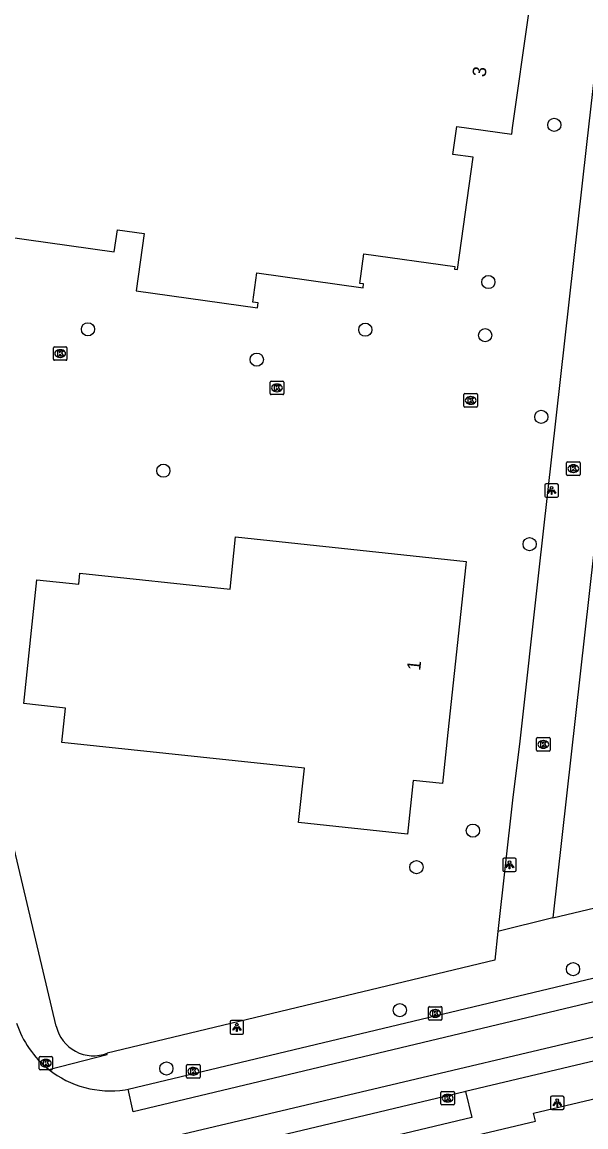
# Model space of a CAD drawing. Extents: x 162082 to 163393, y 388091 to 388632.
# Drawn here: x 162963.6 to 163005.4, y 388261.2 to 388343.1 of the extents above; entities that cross this region are included whole.
import ezdxf

# ---------------------------------------------------------------- set-up
doc = ezdxf.new("R2010")
doc.units = 0
for name, color, linetype in [('IMGEO_Boom', 7, 'Continuous'), ('IMGEO_Kolk', 7, 'Continuous'), ('IMGEO_Lichtpunt', 7, 'Continuous'), ('IMGEO_Pand', 7, 'Continuous'), ('IMGEO_Pand_nummerreeks', 7, 'Continuous'), ('IMGEO_Rijbaan_lokaal_gesloten', 7, 'Continuous'), ('IMGEO_Voetpad_open', 7, 'Continuous')]:
    doc.layers.add(name, color=color, linetype=linetype)

msp = doc.modelspace()

# ---------------------------------------------------------------- linework, layer by layer
at = {"layer": 'IMGEO_Boom'}
for centre in [(163003.085, 388335.514), (162998.2, 388323.859), (162968.519, 388320.354), (162989.078, 388320.325), (162997.959, 388319.915), (162981.031, 388318.106), (163002.121, 388313.858), (162974.111, 388309.867), (163001.259, 388304.418), (162997.055, 388283.177), (162992.866, 388280.467), (163004.475, 388272.897), (162991.638, 388269.857), (162974.33, 388265.53)]:
    msp.add_circle(centre, 0.489, dxfattribs=at)
at = {"layer": 'IMGEO_Kolk'}
for p, q in [((162965.963, 388318.13), (162965.963, 388318.982)), ((162966.038, 388319.056), (162966.89, 388319.056)), ((162966.451, 388318.836), (162966.476, 388318.836)), ((162966.964, 388318.982), (162966.964, 388318.13)), ((162966.89, 388318.056), (162966.038, 388318.056)), ((162966.474, 388318.276), (162966.449, 388318.276)), ((162982.027, 388315.584), (162982.027, 388316.436)), ((162982.102, 388316.51), (162982.954, 388316.51)), ((162982.515, 388316.29), (162982.54, 388316.29)), ((162983.028, 388316.436), (162983.028, 388315.584)), ((162982.954, 388315.51), (162982.102, 388315.51)), ((162982.538, 388315.73), (162982.513, 388315.73)), ((162996.391, 388314.657), (162996.391, 388315.509)), ((162996.466, 388315.583), (162997.318, 388315.583)), ((162997.392, 388315.509), (162997.392, 388314.657)), ((162997.318, 388314.583), (162996.466, 388314.583)), ((162996.902, 388314.803), (162996.877, 388314.803)), ((162996.879, 388315.363), (162996.904, 388315.363)), ((163004.075, 388310.523), (163004.927, 388310.523)), ((163004, 388309.597), (163004, 388310.449)), ((163004.511, 388309.743), (163004.486, 388309.743)), ((163004.488, 388310.303), (163004.513, 388310.303)), ((163005.001, 388310.449), (163005.001, 388309.597)), ((163004.927, 388309.523), (163004.075, 388309.523)), ((163001.772, 388289.146), (163001.772, 388289.998)), ((163001.847, 388290.072), (163002.699, 388290.072)), ((163002.773, 388289.998), (163002.773, 388289.146)), ((163002.283, 388289.292), (163002.258, 388289.292)), ((163002.26, 388289.852), (163002.285, 388289.852)), ((163002.699, 388289.072), (163001.847, 388289.072)), ((162993.76, 388269.194), (162993.76, 388270.046)), ((162993.835, 388270.12), (162994.687, 388270.12)), ((162994.248, 388269.9), (162994.273, 388269.9)), ((162994.761, 388270.046), (162994.761, 388269.194)), ((162994.687, 388269.12), (162993.835, 388269.12)), ((162994.271, 388269.34), (162994.246, 388269.34)), ((162964.898, 388265.5), (162964.898, 388266.352)), ((162964.973, 388266.426), (162965.825, 388266.426)), ((162965.899, 388266.352), (162965.899, 388265.5)), ((162965.825, 388265.426), (162964.973, 388265.426)), ((162965.409, 388265.646), (162965.384, 388265.646)), ((162965.386, 388266.206), (162965.411, 388266.206)), ((162975.829, 388264.9), (162975.829, 388265.752)), ((162975.904, 388265.826), (162976.756, 388265.826)), ((162976.317, 388265.606), (162976.342, 388265.606)), ((162976.83, 388265.752), (162976.83, 388264.9)), ((162976.756, 388264.826), (162975.904, 388264.826)), ((162976.34, 388265.046), (162976.315, 388265.046)), ((162994.682, 388262.912), (162994.682, 388263.764)), ((162994.757, 388263.838), (162995.609, 388263.838)), ((162995.683, 388263.764), (162995.683, 388262.912)), ((162995.193, 388263.058), (162995.168, 388263.058)), ((162995.17, 388263.618), (162995.195, 388263.618)), ((162995.609, 388262.838), (162994.757, 388262.838))]:
    msp.add_line(p, q, dxfattribs=at)
for points in [[(162965.963, 388318.13), (162965.963, 388318.982)], [(162966.038, 388319.056), (162966.89, 388319.056)], [(162966.284, 388318.756), (162966.407, 388318.756), (162966.407, 388318.605), (162966.537, 388318.756), (162966.701, 388318.756), (162966.555, 388318.605), (162966.708, 388318.356), (162966.556, 388318.356), (162966.471, 388318.52), (162966.407, 388318.453), (162966.407, 388318.356), (162966.284, 388318.356), (162966.284, 388318.756)], [(162966.964, 388318.982), (162966.964, 388318.13)], [(162966.89, 388318.056), (162966.038, 388318.056)], [(162982.027, 388315.584), (162982.027, 388316.436)], [(162982.102, 388316.51), (162982.954, 388316.51)], [(162982.348, 388316.21), (162982.471, 388316.21), (162982.471, 388316.059), (162982.601, 388316.21), (162982.765, 388316.21), (162982.619, 388316.059), (162982.772, 388315.81), (162982.62, 388315.81), (162982.535, 388315.974), (162982.471, 388315.907), (162982.471, 388315.81), (162982.348, 388315.81), (162982.348, 388316.21)], [(162983.028, 388316.436), (162983.028, 388315.584)], [(162982.954, 388315.51), (162982.102, 388315.51)], [(162996.391, 388314.657), (162996.391, 388315.509)], [(162996.466, 388315.583), (162997.318, 388315.583)], [(162997.392, 388315.509), (162997.392, 388314.657)], [(162997.318, 388314.583), (162996.466, 388314.583)], [(162996.712, 388315.283), (162996.835, 388315.283), (162996.835, 388315.132), (162996.965, 388315.283), (162997.129, 388315.283), (162996.983, 388315.132), (162997.136, 388314.883), (162996.984, 388314.883), (162996.899, 388315.047), (162996.835, 388314.98), (162996.835, 388314.883), (162996.712, 388314.883), (162996.712, 388315.283)], [(163004.075, 388310.523), (163004.927, 388310.523)], [(163004, 388309.597), (163004, 388310.449)], [(163004.321, 388310.223), (163004.444, 388310.223), (163004.444, 388310.072), (163004.574, 388310.223), (163004.738, 388310.223), (163004.592, 388310.072), (163004.745, 388309.823), (163004.593, 388309.823), (163004.508, 388309.987), (163004.444, 388309.92), (163004.444, 388309.823), (163004.321, 388309.823), (163004.321, 388310.223)], [(163005.001, 388310.449), (163005.001, 388309.597)], [(163004.927, 388309.523), (163004.075, 388309.523)], [(163001.772, 388289.146), (163001.772, 388289.998)], [(163001.847, 388290.072), (163002.699, 388290.072)], [(163002.773, 388289.998), (163002.773, 388289.146)], [(163002.093, 388289.772), (163002.216, 388289.772), (163002.216, 388289.621), (163002.346, 388289.772), (163002.51, 388289.772), (163002.364, 388289.621), (163002.517, 388289.372), (163002.365, 388289.372), (163002.28, 388289.536), (163002.216, 388289.469), (163002.216, 388289.372), (163002.093, 388289.372), (163002.093, 388289.772)], [(163002.699, 388289.072), (163001.847, 388289.072)], [(162993.76, 388269.194), (162993.76, 388270.046)], [(162993.835, 388270.12), (162994.687, 388270.12)], [(162994.081, 388269.82), (162994.204, 388269.82), (162994.204, 388269.669), (162994.334, 388269.82), (162994.498, 388269.82), (162994.352, 388269.669), (162994.505, 388269.42), (162994.353, 388269.42), (162994.268, 388269.584), (162994.204, 388269.517), (162994.204, 388269.42), (162994.081, 388269.42), (162994.081, 388269.82)], [(162994.761, 388270.046), (162994.761, 388269.194)], [(162994.687, 388269.12), (162993.835, 388269.12)], [(162964.898, 388265.5), (162964.898, 388266.352)], [(162964.973, 388266.426), (162965.825, 388266.426)], [(162965.899, 388266.352), (162965.899, 388265.5)], [(162965.825, 388265.426), (162964.973, 388265.426)], [(162965.219, 388266.126), (162965.342, 388266.126), (162965.342, 388265.975), (162965.472, 388266.126), (162965.636, 388266.126), (162965.49, 388265.975), (162965.643, 388265.726), (162965.491, 388265.726), (162965.406, 388265.89), (162965.342, 388265.823), (162965.342, 388265.726), (162965.219, 388265.726), (162965.219, 388266.126)], [(162975.829, 388264.9), (162975.829, 388265.752)], [(162975.904, 388265.826), (162976.756, 388265.826)], [(162976.15, 388265.526), (162976.273, 388265.526), (162976.273, 388265.375), (162976.403, 388265.526), (162976.567, 388265.526), (162976.421, 388265.375), (162976.574, 388265.126), (162976.422, 388265.126), (162976.337, 388265.29), (162976.273, 388265.223), (162976.273, 388265.126), (162976.15, 388265.126), (162976.15, 388265.526)], [(162976.83, 388265.752), (162976.83, 388264.9)], [(162976.756, 388264.826), (162975.904, 388264.826)], [(162994.682, 388262.912), (162994.682, 388263.764)], [(162994.757, 388263.838), (162995.609, 388263.838)], [(162995.683, 388263.764), (162995.683, 388262.912)], [(162995.003, 388263.538), (162995.126, 388263.538), (162995.126, 388263.387), (162995.256, 388263.538), (162995.42, 388263.538), (162995.274, 388263.387), (162995.427, 388263.138), (162995.275, 388263.138), (162995.19, 388263.302), (162995.126, 388263.235), (162995.126, 388263.138), (162995.003, 388263.138), (162995.003, 388263.538)], [(162995.609, 388262.838), (162994.757, 388262.838)]]:
    msp.add_lwpolyline(points, dxfattribs=at)
for centre, start, end in [((162966.04, 388318.98), 91.55205, 178.44795), ((162966.04, 388318.98), 91.55205, 178.44795), ((162966.888, 388318.98), 1.55205, 88.44795), ((162966.888, 388318.98), 1.55205, 88.44795), ((162966.04, 388318.132), 181.55205, 268.44795), ((162966.04, 388318.132), 181.55205, 268.44795), ((162966.888, 388318.132), 271.55205, 358.44795), ((162966.888, 388318.132), 271.55205, 358.44795), ((162982.104, 388316.434), 91.55205, 178.44795), ((162982.104, 388316.434), 91.55205, 178.44795), ((162982.952, 388316.434), 1.55205, 88.44795), ((162982.952, 388316.434), 1.55205, 88.44795), ((162982.104, 388315.586), 181.55205, 268.44795), ((162982.104, 388315.586), 181.55205, 268.44795), ((162982.952, 388315.586), 271.55205, 358.44795), ((162982.952, 388315.586), 271.55205, 358.44795), ((162996.468, 388315.507), 91.55205, 178.44795), ((162996.468, 388315.507), 91.55205, 178.44795), ((162997.316, 388315.507), 1.55205, 88.44795), ((162997.316, 388315.507), 1.55205, 88.44795), ((162996.468, 388314.659), 181.55205, 268.44795), ((162996.468, 388314.659), 181.55205, 268.44795), ((162997.316, 388314.659), 271.55205, 358.44795), ((162997.316, 388314.659), 271.55205, 358.44795), ((163004.077, 388310.447), 91.55205, 178.44795), ((163004.077, 388310.447), 91.55205, 178.44795), ((163004.925, 388310.447), 1.55205, 88.44795), ((163004.925, 388310.447), 1.55205, 88.44795), ((163004.077, 388309.599), 181.55205, 268.44795), ((163004.077, 388309.599), 181.55205, 268.44795), ((163004.925, 388309.599), 271.55205, 358.44795), ((163004.925, 388309.599), 271.55205, 358.44795), ((163001.849, 388289.996), 91.55205, 178.44795), ((163001.849, 388289.996), 91.55205, 178.44795), ((163002.697, 388289.996), 1.55205, 88.44795), ((163002.697, 388289.996), 1.55205, 88.44795), ((163001.849, 388289.148), 181.55205, 268.44795), ((163001.849, 388289.148), 181.55205, 268.44795), ((163002.697, 388289.148), 271.55205, 358.44795), ((163002.697, 388289.148), 271.55205, 358.44795), ((162993.837, 388270.044), 91.55205, 178.44795), ((162993.837, 388270.044), 91.55205, 178.44795), ((162994.685, 388270.044), 1.55205, 88.44795), ((162994.685, 388270.044), 1.55205, 88.44795), ((162993.837, 388269.196), 181.55205, 268.44795), ((162993.837, 388269.196), 181.55205, 268.44795), ((162994.685, 388269.196), 271.55205, 358.44795), ((162994.685, 388269.196), 271.55205, 358.44795), ((162964.975, 388266.35), 91.55205, 178.44795), ((162964.975, 388266.35), 91.55205, 178.44795), ((162965.823, 388266.35), 1.55205, 88.44795), ((162965.823, 388266.35), 1.55205, 88.44795), ((162964.975, 388265.502), 181.55205, 268.44795), ((162964.975, 388265.502), 181.55205, 268.44795), ((162965.823, 388265.502), 271.55205, 358.44795), ((162965.823, 388265.502), 271.55205, 358.44795), ((162975.906, 388265.75), 91.55205, 178.44795), ((162975.906, 388265.75), 91.55205, 178.44795), ((162976.754, 388265.75), 1.55205, 88.44795), ((162976.754, 388265.75), 1.55205, 88.44795), ((162975.906, 388264.902), 181.55205, 268.44795), ((162975.906, 388264.902), 181.55205, 268.44795), ((162976.754, 388264.902), 271.55205, 358.44795), ((162976.754, 388264.902), 271.55205, 358.44795), ((162994.759, 388263.762), 91.55205, 178.44795), ((162994.759, 388263.762), 91.55205, 178.44795), ((162995.607, 388263.762), 1.55205, 88.44795), ((162995.607, 388263.762), 1.55205, 88.44795), ((162994.759, 388262.914), 181.55205, 268.44795), ((162994.759, 388262.914), 181.55205, 268.44795), ((162995.607, 388262.914), 271.55205, 358.44795), ((162995.607, 388262.914), 271.55205, 358.44795)]:
    msp.add_arc(centre, 0.0765, start, end, dxfattribs=at)
for centre, major_axis, ratio, start_param, end_param in [((162966.45, 388318.556), (-0.387, 0.002), 0.722429, 4.712389, 7.853982), ((162966.475, 388318.556), (-0.39, 0.002), 0.717154, 1.570796, 4.712389), ((162982.514, 388316.01), (-0.387, 0.002), 0.722429, 4.712389, 7.853982), ((162982.539, 388316.01), (-0.39, 0.002), 0.717154, 1.570796, 4.712389), ((162996.878, 388315.083), (-0.387, 0.002), 0.722429, 4.712389, 7.853982), ((162996.903, 388315.083), (-0.39, 0.002), 0.717154, 1.570796, 4.712389), ((163004.487, 388310.023), (-0.387, 0.002), 0.722429, 4.712389, 7.853982), ((163004.512, 388310.023), (-0.39, 0.002), 0.717154, 1.570796, 4.712389), ((163002.259, 388289.572), (-0.387, 0.002), 0.722429, 4.712389, 7.853982), ((163002.284, 388289.572), (-0.39, 0.002), 0.717154, 1.570796, 4.712389), ((162994.247, 388269.62), (-0.387, 0.002), 0.722429, 4.712389, 7.853982), ((162994.272, 388269.62), (-0.39, 0.002), 0.717154, 1.570796, 4.712389), ((162965.385, 388265.926), (-0.387, 0.002), 0.722429, 4.712389, 7.853982), ((162965.41, 388265.926), (-0.39, 0.002), 0.717154, 1.570796, 4.712389), ((162976.316, 388265.326), (-0.387, 0.002), 0.722429, 4.712389, 7.853982), ((162976.341, 388265.326), (-0.39, 0.002), 0.717154, 1.570796, 4.712389), ((162995.169, 388263.338), (-0.387, 0.002), 0.722429, 4.712389, 7.853982), ((162995.194, 388263.338), (-0.39, 0.002), 0.717154, 1.570796, 4.712389)]:
    msp.add_ellipse(centre, major_axis=major_axis, ratio=ratio, start_param=start_param, end_param=end_param, dxfattribs=at)
at = {"layer": 'IMGEO_Lichtpunt'}
for p, q in [((163003.294, 388308.894), (163002.486, 388308.894)), ((163003.294, 388308.894), (163002.486, 388308.894)), ((163002.392, 388308.799), (163002.392, 388307.992)), ((163002.392, 388308.799), (163002.392, 388307.992)), ((163003.388, 388307.992), (163003.388, 388308.799)), ((163003.388, 388307.992), (163003.388, 388308.799)), ((163002.486, 388307.898), (163003.294, 388307.898)), ((163002.486, 388307.898), (163003.294, 388307.898)), ((162999.269, 388281.043), (162999.269, 388280.236)), ((162999.269, 388281.043), (162999.269, 388280.236)), ((163000.171, 388281.138), (162999.363, 388281.138)), ((163000.171, 388281.138), (162999.363, 388281.138)), ((163000.265, 388280.236), (163000.265, 388281.043)), ((163000.265, 388280.236), (163000.265, 388281.043)), ((162999.363, 388280.142), (163000.171, 388280.142)), ((162999.363, 388280.142), (163000.171, 388280.142)), ((162979.062, 388268.991), (162979.062, 388268.184)), ((162979.062, 388268.991), (162979.062, 388268.184)), ((162979.964, 388269.086), (162979.156, 388269.086)), ((162979.964, 388269.086), (162979.156, 388269.086)), ((162980.058, 388268.184), (162980.058, 388268.991)), ((162980.058, 388268.184), (162980.058, 388268.991)), ((162979.156, 388268.09), (162979.964, 388268.09)), ((162979.156, 388268.09), (162979.964, 388268.09)), ((163002.812, 388263.392), (163002.812, 388262.585)), ((163002.812, 388263.392), (163002.812, 388262.585)), ((163003.714, 388263.487), (163002.906, 388263.487)), ((163003.714, 388263.487), (163002.906, 388263.487)), ((163003.808, 388262.585), (163003.808, 388263.392)), ((163003.808, 388262.585), (163003.808, 388263.392)), ((163002.906, 388262.491), (163003.714, 388262.491)), ((163002.906, 388262.491), (163003.714, 388262.491))]:
    msp.add_line(p, q, dxfattribs=at)
for points in [[(163002.766, 388308.463), (163002.805, 388308.435), (163002.617, 388308.173), (163002.579, 388308.2), (163002.766, 388308.463)], [(163002.868, 388308.415), (163002.915, 388308.415), (163002.915, 388308.093), (163002.868, 388308.093), (163002.868, 388308.415)], [(163002.978, 388308.435), (163003.016, 388308.462), (163003.203, 388308.2), (163003.164, 388308.172), (163002.978, 388308.435)], [(162999.643, 388280.707), (162999.682, 388280.679), (162999.494, 388280.417), (162999.456, 388280.444), (162999.643, 388280.707)], [(162999.745, 388280.659), (162999.792, 388280.659), (162999.792, 388280.337), (162999.745, 388280.337), (162999.745, 388280.659)], [(162999.855, 388280.679), (162999.893, 388280.706), (163000.08, 388280.444), (163000.041, 388280.416), (162999.855, 388280.679)], [(162979.436, 388268.655), (162979.475, 388268.627), (162979.287, 388268.365), (162979.249, 388268.392), (162979.436, 388268.655)], [(162979.538, 388268.607), (162979.585, 388268.607), (162979.585, 388268.285), (162979.538, 388268.285), (162979.538, 388268.607)], [(162979.648, 388268.627), (162979.686, 388268.654), (162979.873, 388268.392), (162979.834, 388268.364), (162979.648, 388268.627)], [(163003.186, 388263.056), (163003.225, 388263.028), (163003.037, 388262.766), (163002.999, 388262.793), (163003.186, 388263.056)], [(163003.288, 388263.008), (163003.335, 388263.008), (163003.335, 388262.686), (163003.288, 388262.686), (163003.288, 388263.008)], [(163003.398, 388263.028), (163003.436, 388263.055), (163003.623, 388262.793), (163003.584, 388262.765), (163003.398, 388263.028)]]:
    msp.add_lwpolyline(points, dxfattribs=at)
for centre in [(163002.891, 388308.597), (162999.768, 388280.841), (162979.561, 388268.789), (163003.311, 388263.19)]:
    msp.add_circle(centre, 0.0994, dxfattribs=at)
for centre, start, end in [((163002.486, 388308.799), 90, 180), ((163002.486, 388308.799), 90, 180), ((163003.294, 388308.799), 0, 90), ((163003.294, 388308.799), 0, 90), ((163002.486, 388307.992), 180, 270), ((163002.486, 388307.992), 180, 270), ((163003.294, 388307.992), 270, 0), ((163003.294, 388307.992), 270, 360), ((162999.363, 388281.043), 90, 180), ((162999.363, 388281.043), 90, 180), ((163000.171, 388281.043), 0, 90), ((163000.171, 388281.043), 0, 90), ((162999.363, 388280.236), 180, 270), ((162999.363, 388280.236), 180, 270), ((163000.171, 388280.236), 270, 0), ((163000.171, 388280.236), 270, 360), ((162979.156, 388268.991), 90, 180), ((162979.156, 388268.991), 90, 180), ((162979.964, 388268.991), 0, 90), ((162979.964, 388268.991), 0, 90), ((162979.156, 388268.184), 180, 270), ((162979.156, 388268.184), 180, 270), ((162979.964, 388268.184), 270, 0), ((162979.964, 388268.184), 270, 360), ((163002.906, 388263.392), 90, 180), ((163002.906, 388263.392), 90, 180), ((163003.714, 388263.392), 0, 90), ((163003.714, 388263.392), 0, 90), ((163002.906, 388262.585), 180, 270), ((163002.906, 388262.585), 180, 270), ((163003.714, 388262.585), 270, 0), ((163003.714, 388262.585), 270, 360)]:
    msp.add_arc(centre, 0.0946, start, end, dxfattribs=at)
at = {"layer": 'IMGEO_Pand'}
for points in [[(162962.21, 388327.258), (162970.473, 388326.096), (162970.705, 388327.745), (162972.698, 388327.465), (162972.099, 388323.204), (162981.092, 388321.94), (162981.146, 388322.322), (162980.734, 388322.38), (162981.036, 388324.532), (162988.911, 388323.425), (162988.952, 388323.716), (162988.67, 388323.755), (162988.979, 388325.951), (162995.709, 388325.005), (162995.684, 388324.824), (162995.914, 388324.792), (162997.084, 388333.113), (162995.569, 388333.326), (162995.862, 388335.406), (162999.936, 388334.833), (163000, 388335.288), (163001.195, 388343.791)], [(162996.548, 388303.138), (162996.52, 388302.879), (162995.194, 388290.457), (162994.79, 388286.669), (162992.627, 388286.9), (162992.201, 388282.906), (162984.128, 388283.768), (162984.559, 388287.803), (162966.581, 388289.722), (162966.852, 388292.264), (162964.864, 388292.476), (162963.755, 388292.594), (162964.735, 388301.773), (162967.832, 388301.442), (162967.921, 388302.275), (162979.053, 388301.087), (162979.466, 388304.962), (162996.548, 388303.138)]]:
    msp.add_lwpolyline(points, dxfattribs=at)
at = {"layer": 'IMGEO_Rijbaan_lokaal_gesloten'}
for points in [[(163022.672, 388276.234), (163023.09, 388274.56), (162971.872, 388262.319), (162971.492, 388264.011)], [(162971.492, 388264.011), (163008.218, 388272.782)], [(162972.884, 388258.2), (162972.452, 388259.959), (163023.671, 388272.065), (163024.112, 388270.399)], [(163009.956, 388267.016), (162996.51, 388263.828)], [(162971.268, 388263.958), (162971.492, 388264.011)], [(162996.51, 388263.828), (162996.44, 388263.811), (162972.884, 388258.2)]]:
    msp.add_lwpolyline(points, dxfattribs=at)
for centre, radius, start, end in [((162970.158, 388271.174), 7.293, 198.11171, 231.48453), ((162970.171, 388271.182), 7.307, 231.44456, 278.63455)]:
    msp.add_arc(centre, radius, start, end, dxfattribs=at)
at = {"layer": 'IMGEO_Voetpad_open'}
for points in [[(163009.556, 388370.497), (163009.548, 388370.428), (163008.683, 388363.066), (163008.493, 388360.713), (163005.462, 388334.056), (163001.924, 388302.296), (163000.525, 388289.822), (163000, 388285.427), (162998.906, 388275.686)], [(163013.441, 388370.076), (163002.97, 388276.7)], [(162966.17, 388268.679), (162961.187, 388289.582), (162960.82, 388291.119), (162953.166, 388323.228), (162952.976, 388324.023)], [(163002.97, 388276.7), (163142.597, 388309.979)], [(163002.97, 388276.7), (162998.906, 388275.686)], [(162998.906, 388275.686), (162998.667, 388273.56), (162969.954, 388266.671)], [(162986.413, 388255.159), (162985.767, 388257.851), (163001.699, 388261.631), (163001.557, 388262.213), (163019.583, 388266.507), (163023.493, 388267.421)], [(162965.617, 388265.468), (162969.935, 388266.571), (162969.954, 388266.671)], [(162996.51, 388263.828), (162996.971, 388261.896), (162955.043, 388251.888), (162954.592, 388253.843)]]:
    msp.add_lwpolyline(points, dxfattribs=at)
msp.add_arc((162968.929, 388269.308), 2.83, 192.849, 291.24521, dxfattribs=at)

# ---------------------------------------------------------------- texts
at = {"layer": 'IMGEO_Pand_nummerreeks'}
for s, rotation, p in [('3', 82.00172, (162997.981, 388339.026)), ('1', 83.90967, (162993.146, 388295.011))]:
    msp.add_text(s, height=1, rotation=rotation, dxfattribs=at).set_placement(p)

doc.saveas('drawing.dxf')
